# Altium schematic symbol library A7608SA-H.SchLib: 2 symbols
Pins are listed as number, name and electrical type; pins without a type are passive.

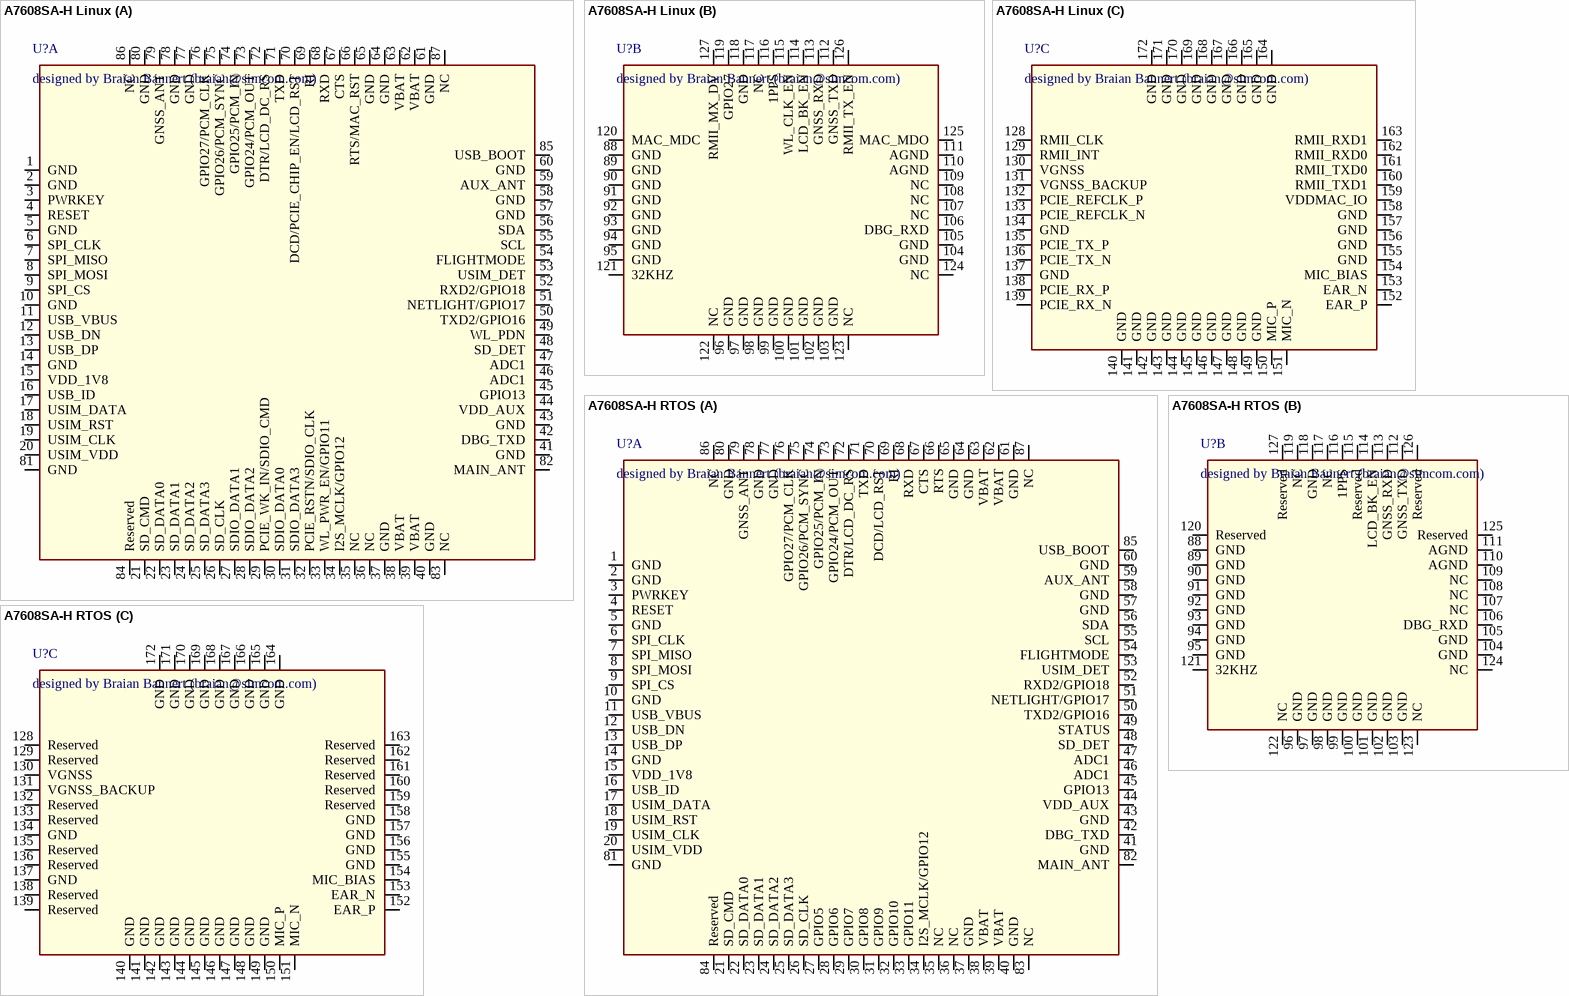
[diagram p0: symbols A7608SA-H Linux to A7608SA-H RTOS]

## A7608SA-H Linux
designator U?, comment designed by Braian Bannert (braian@simcom.com)
footprint A7608SA-H RTOS
part A pins: 1 GND, 2 GND, 3 PWRKEY, 4 RESET, 5 GND, 6 SPI_CLK, 7 SPI_MISO, 8 SPI_MOSI, 9 SPI_CS, 10 GND, 11 USB_VBUS, 12 USB_DN, 13 USB_DP, 14 GND, 15 VDD_1V8, 16 USB_ID, 17 USIM_DATA, 18 USIM_RST, 19 USIM_CLK, 20 USIM_VDD, 21 SD_CMD, 22 SD_DATA0, 23 SD_DATA1, 24 SD_DATA2, 25 SD_DATA3, 26 SD_CLK, 27 SDIO_DATA1, 28 SDIO_DATA2, 29 PCIE_WK_IN/SDIO_CMD, 30 SDIO_DATA0, 31 SDIO_DATA3, 32 PCIE_RSTN/SDIO_CLK, 33 WL_PWR_EN/GPIO11, 34 I2S_MCLK/GPIO12, 35 NC, 36 NC, 37 GND, 38 VBAT, 39 VBAT, 40 GND, 41 GND, 42 DBG_TXD, 43 GND, 44 VDD_AUX, 45 GPIO13, 46 ADC1, 47 ADC1, 48 SD_DET, 49 WL_PDN, 50 TXD2/GPIO16, 51 NETLIGHT/GPIO17, 52 RXD2/GPIO18, 53 USIM_DET, 54 FLIGHTMODE, 55 SCL, 56 SDA, 57 GND, 58 GND, 59 AUX_ANT, 60 GND, 61 GND, 62 VBAT, 63 VBAT, 64 GND, 65 GND, 66 RTS/MAC_RST, 67 CTS, 68 RXD, 69 RI, 70 DCD/PCIE_CHIP_EN/LCD_RST, 71 TXD, 72 DTR/LCD_DC_RS, 73 GPIO24/PCM_OUT, 74 GPIO25/PCM_IN, 75 GPIO26/PCM_SYNC, 76 GPIO27/PCM_CLK, 77 GND, 78 GND, 79 GNSS_ANT, 80 GND, 81 GND, 82 MAIN_ANT, 83 NC, 84 Reserved, 85 USB_BOOT, 86 NC, 87 NC
part B pins: 88 GND, 89 GND, 90 GND, 91 GND, 92 GND, 93 GND, 94 GND, 95 GND, 96 GND, 97 GND, 98 GND, 99 GND, 100 GND, 101 GND, 102 GND, 103 GND, 104 GND, 105 GND, 106 DBG_RXD, 107 NC, 108 NC, 109 NC, 110 AGND, 111 AGND, 112 GNSS_TXD, 113 GNSS_RXD, 114 LCD_BK_EN, 115 WL_CLK_EN, 116 1PPS, 117 NC, 118 GND, 119 GPIO27, 120 MAC_MDC, 121 32KHZ, 122 NC, 123 NC, 124 NC, 125 MAC_MDO, 126 RMII_TX_EN, 127 RMII_MX_DV
part C pins: 128 RMII_CLK, 129 RMII_INT, 130 VGNSS, 131 VGNSS_BACKUP, 132 PCIE_REFCLK_P, 133 PCIE_REFCLK_N, 134 GND, 135 PCIE_TX_P, 136 PCIE_TX_N, 137 GND, 138 PCIE_RX_P, 139 PCIE_RX_N, 140 GND, 141 GND, 142 GND, 143 GND, 144 GND, 145 GND, 146 GND, 147 GND, 148 GND, 149 GND, 150 MIC_P, 151 MIC_N, 152 EAR_P, 153 EAR_N, 154 MIC_BIAS, 155 GND, 156 GND, 157 GND, 158 GND, 159 VDDMAC_IO, 160 RMII_TXD1, 161 RMII_TXD0, 162 RMII_RXD0, 163 RMII_RXD1, 164 GND, 165 GND, 166 GND, 167 GND, 168 GND, 169 GND, 170 GND, 171 GND, 172 GND

## A7608SA-H RTOS
designator U?, comment designed by Braian Bannert (braian@simcom.com)
footprint A7608SA-H RTOS
part A pins: 1 GND, 2 GND, 3 PWRKEY, 4 RESET, 5 GND, 6 SPI_CLK, 7 SPI_MISO, 8 SPI_MOSI, 9 SPI_CS, 10 GND, 11 USB_VBUS, 12 USB_DN, 13 USB_DP, 14 GND, 15 VDD_1V8, 16 USB_ID, 17 USIM_DATA, 18 USIM_RST, 19 USIM_CLK, 20 USIM_VDD, 21 SD_CMD, 22 SD_DATA0, 23 SD_DATA1, 24 SD_DATA2, 25 SD_DATA3, 26 SD_CLK, 27 GPIO5, 28 GPIO6, 29 GPIO7, 30 GPIO8, 31 GPIO9, 32 GPIO10, 33 GPIO11, 34 I2S_MCLK/GPIO12, 35 NC, 36 NC, 37 GND, 38 VBAT, 39 VBAT, 40 GND, 41 GND, 42 DBG_TXD, 43 GND, 44 VDD_AUX, 45 GPIO13, 46 ADC1, 47 ADC1, 48 SD_DET, 49 STATUS, 50 TXD2/GPIO16, 51 NETLIGHT/GPIO17, 52 RXD2/GPIO18, 53 USIM_DET, 54 FLIGHTMODE, 55 SCL, 56 SDA, 57 GND, 58 GND, 59 AUX_ANT, 60 GND, 61 GND, 62 VBAT, 63 VBAT, 64 GND, 65 GND, 66 RTS, 67 CTS, 68 RXD, 69 RI, 70 DCD/LCD_RST, 71 TXD, 72 DTR/LCD_DC_RS, 73 GPIO24/PCM_OUT, 74 GPIO25/PCM_IN, 75 GPIO26/PCM_SYNC, 76 GPIO27/PCM_CLK, 77 GND, 78 GND, 79 GNSS_ANT, 80 GND, 81 GND, 82 MAIN_ANT, 83 NC, 84 Reserved, 85 USB_BOOT, 86 NC, 87 NC
part B pins: 88 GND, 89 GND, 90 GND, 91 GND, 92 GND, 93 GND, 94 GND, 95 GND, 96 GND, 97 GND, 98 GND, 99 GND, 100 GND, 101 GND, 102 GND, 103 GND, 104 GND, 105 GND, 106 DBG_RXD, 107 NC, 108 NC, 109 NC, 110 AGND, 111 AGND, 112 GNSS_TXD, 113 GNSS_RXD, 114 LCD_BK_EN, 115 Reserved, 116 1PPS, 117 NC, 118 GND, 119 NC, 120 Reserved, 121 32KHZ, 122 NC, 123 NC, 124 NC, 125 Reserved, 126 Reserved, 127 Reserved
part C pins: 128 Reserved, 129 Reserved, 130 VGNSS, 131 VGNSS_BACKUP, 132 Reserved, 133 Reserved, 134 GND, 135 Reserved, 136 Reserved, 137 GND, 138 Reserved, 139 Reserved, 140 GND, 141 GND, 142 GND, 143 GND, 144 GND, 145 GND, 146 GND, 147 GND, 148 GND, 149 GND, 150 MIC_P, 151 MIC_N, 152 EAR_P, 153 EAR_N, 154 MIC_BIAS, 155 GND, 156 GND, 157 GND, 158 GND, 159 Reserved, 160 Reserved, 161 Reserved, 162 Reserved, 163 Reserved, 164 GND, 165 GND, 166 GND, 167 GND, 168 GND, 169 GND, 170 GND, 171 GND, 172 GND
